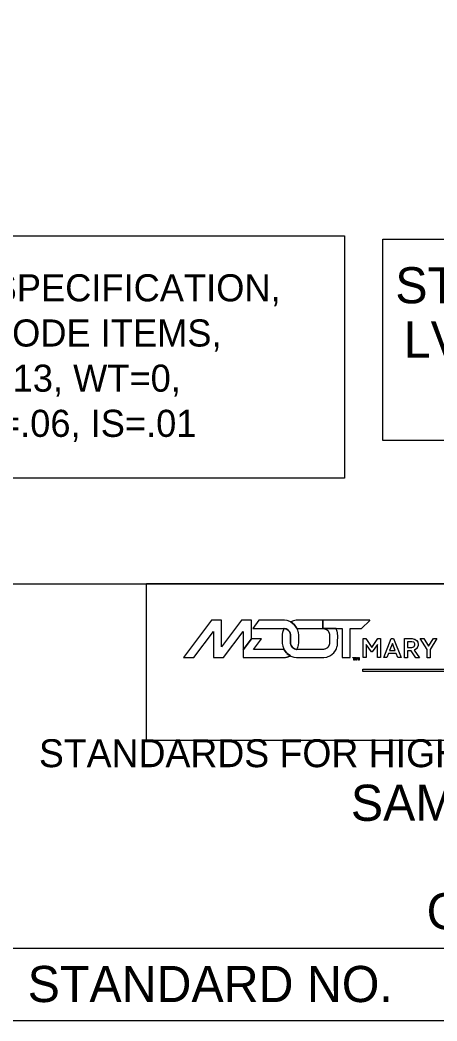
# Model space of a CAD drawing. Extents: x -0.5 to 19.9, y 5.2 to 17.3.
# Drawn here: x 3.628 to 5.013, y 5.937 to 9.261 of the extents above; entities that cross this region are included whole.
import ezdxf

# ---------------------------------------------------------------- set-up
doc = ezdxf.new("R2010")
doc.units = 0
for name, color, linetype in [('BORD-LINE', 7, 'Continuous'), ('DETL-NOTE', 7, 'Continuous'), ('MSHA-LOGO', 7, 'Continuous'), ('TTLB-TEXT', 7, 'Continuous'), ('USER-BORD', 7, 'Continuous'), ('USER-LINE', 7, 'Continuous')]:
    doc.layers.add(name, color=color, linetype=linetype)

msp = doc.modelspace()

# ---------------------------------------------------------------- linework, layer by layer
at = {"layer": 'BORD-LINE'}
msp.add_line((7.7685, 7.3883), (0.3943, 7.3883), dxfattribs=at)
at = {"layer": 'MSHA-LOGO'}
for points in [[(4.3697, 7.1699), (4.3968, 7.206), (4.3968, 7.2687), (4.3638, 7.2687), (4.3434, 7.2413), (4.2975, 7.1802), (4.2975, 7.2687), (4.2646, 7.2687), (4.1714, 7.1444), (4.2053, 7.1444), (4.2704, 7.2312), (4.2704, 7.1444), (4.3046, 7.1444), (4.3697, 7.2312)], [(4.5048, 7.2408), (4.5056, 7.2408), (4.5132, 7.2388), (4.5139, 7.2384), (4.5147, 7.238), (4.5185, 7.2352), (4.5217, 7.2319), (4.5223, 7.2312), (4.5229, 7.2303), (4.5251, 7.2256), (4.5263, 7.2205), (4.5264, 7.2195), (4.5264, 7.2195), (4.5264, 7.2193), (4.5264, 7.2193), (4.5264, 7.219), (4.5264, 7.2184), (4.5264, 7.2182), (4.5264, 7.1947), (4.5264, 7.1944), (4.5264, 7.1938), (4.5264, 7.1936), (4.5264, 7.1936), (4.5264, 7.1934), (4.5264, 7.1934), (4.5264, 7.1929), (4.5262, 7.1918), (4.5262, 7.1914), (4.5265, 7.1894), (4.5287, 7.1838), (4.5334, 7.1776), (4.5402, 7.1731), (4.5463, 7.1712), (4.5476, 7.1711), (4.5479, 7.1715), (4.5481, 7.1717), (4.5481, 7.1717), (4.5483, 7.1722), (4.5503, 7.1766), (4.5505, 7.1771), (4.5506, 7.1776), (4.552, 7.1823), (4.5522, 7.1828), (4.5522, 7.183), (4.5528, 7.1854), (4.5529, 7.1857), (4.553, 7.1864), (4.5537, 7.1927), (4.5537, 7.1948), (4.5537, 7.2179), (4.5537, 7.2202), (4.553, 7.2263), (4.5529, 7.227), (4.5528, 7.2273), (4.5523, 7.2297), (4.5522, 7.23), (4.552, 7.2304), (4.5506, 7.2352), (4.5505, 7.2356), (4.5503, 7.2361), (4.5483, 7.2406), (4.5481, 7.241), (4.5468, 7.2433), (4.5389, 7.2535), (4.5287, 7.2615), (4.5264, 7.2627), (4.5247, 7.2636), (4.5155, 7.2668), (4.5066, 7.2682), (4.5036, 7.2682), (4.4217, 7.2682), (4.4013, 7.241), (4.5036, 7.241), (4.5037, 7.2409), (4.5045, 7.2408)], [(4.5482, 7.2406), (4.5487, 7.2406), (4.5489, 7.2406), (4.6329, 7.2406), (4.633, 7.2406), (4.6333, 7.2406), (4.6334, 7.2406), (4.6335, 7.241), (4.6335, 7.268), (4.6335, 7.268), (4.633, 7.268), (4.6329, 7.268), (4.5489, 7.268), (4.5459, 7.268), (4.537, 7.2666), (4.5278, 7.2634), (4.5264, 7.2627), (4.5287, 7.2615), (4.5389, 7.2535), (4.5468, 7.2433), (4.5481, 7.241)], [(4.6335, 7.268), (4.6335, 7.2408), (4.6979, 7.2408), (4.6979, 7.1444), (4.7249, 7.1444), (4.7249, 7.2408), (4.7625, 7.2408), (4.7895, 7.2678), (4.7895, 7.268)], [(4.5269, 7.1499), (4.5268, 7.1499), (4.5266, 7.15), (4.5266, 7.1501), (4.5254, 7.1507), (4.5151, 7.1582), (4.5142, 7.1592), (4.5133, 7.1601), (4.5059, 7.1703), (4.5053, 7.1714), (4.5052, 7.1714), (4.5049, 7.1714), (4.5048, 7.1714), (4.5045, 7.1714), (4.5038, 7.1714), (4.5036, 7.1714), (4.4042, 7.1714), (4.4306, 7.2064), (4.3966, 7.2064), (4.3695, 7.1704), (4.3695, 7.1442), (4.5034, 7.1442), (4.5042, 7.1442), (4.5062, 7.1443), (4.5065, 7.1444), (4.5072, 7.1444), (4.5092, 7.1447), (4.5094, 7.1447), (4.5096, 7.1447), (4.5101, 7.1449), (4.5103, 7.1449), (4.5104, 7.1449), (4.512, 7.1452), (4.5122, 7.1452), (4.5124, 7.1452), (4.513, 7.1454), (4.5132, 7.1454), (4.5133, 7.1455), (4.5148, 7.1457), (4.5149, 7.1457), (4.515, 7.1458), (4.5158, 7.1461), (4.5159, 7.1461), (4.5161, 7.1461), (4.5174, 7.1466), (4.5175, 7.1466), (4.5176, 7.1467), (4.5184, 7.1469), (4.5185, 7.1469), (4.5186, 7.147), (4.5199, 7.1474), (4.5201, 7.1475), (4.5201, 7.1475), (4.521, 7.1478), (4.5211, 7.1478), (4.5212, 7.1479), (4.5227, 7.1485), (4.5228, 7.1485), (4.5229, 7.1485), (4.5236, 7.1488), (4.5237, 7.1489), (4.5239, 7.1489), (4.5259, 7.1499), (4.5261, 7.1501), (4.5262, 7.15), (4.5267, 7.1499)], [(4.7677, 7.2075), (4.7766, 7.2075), (4.7968, 7.1779), (4.8165, 7.2075), (4.825, 7.2075), (4.825, 7.144), (4.8152, 7.144), (4.8152, 7.1881), (4.7978, 7.1628), (4.7952, 7.1628), (4.7775, 7.1881), (4.7775, 7.144), (4.7677, 7.144)], [(4.8613, 7.2075), (4.8688, 7.2075), (4.8937, 7.144), (4.8832, 7.144), (4.8777, 7.1582), (4.8518, 7.1582), (4.8463, 7.144), (4.8361, 7.144)], [(4.8558, 7.1674), (4.8744, 7.1674), (4.8649, 7.1914)], [(4.9052, 7.1437), (4.9052, 7.2072), (4.9274, 7.2072), (4.9302, 7.2072), (4.9377, 7.2058), (4.9386, 7.2055), (4.9393, 7.2053), (4.945, 7.2014), (4.9454, 7.2009), (4.9458, 7.2004), (4.9488, 7.1952), (4.949, 7.1947), (4.9492, 7.1941), (4.95, 7.1889), (4.95, 7.1871), (4.95, 7.1842), (4.9473, 7.1764), (4.9467, 7.1756), (4.9462, 7.1748), (4.9385, 7.169), (4.9376, 7.1687), (4.9546, 7.1433), (4.9425, 7.1433), (4.9271, 7.1667), (4.915, 7.1667), (4.915, 7.1433), (4.9052, 7.1433)], [(4.915, 7.197), (4.915, 7.1776), (4.9278, 7.1776), (4.9299, 7.1776), (4.936, 7.1798), (4.9366, 7.1802), (4.9371, 7.1806), (4.9399, 7.186), (4.9399, 7.1878), (4.9399, 7.1895), (4.9374, 7.1943), (4.9369, 7.1947), (4.9364, 7.1951), (4.9297, 7.197), (4.9274, 7.197)], [(4.9899, 7.1713), (4.9899, 7.1437), (4.9801, 7.1437), (4.9801, 7.1713), (4.9572, 7.2075), (4.9693, 7.2075), (4.985, 7.1822), (5.0011, 7.2075), (5.0128, 7.2075)], [(4.7335, 7.1444), (4.7424, 7.1444), (4.7424, 7.1428), (4.739, 7.1428), (4.739, 7.1354), (4.7372, 7.1354), (4.7372, 7.1428), (4.7335, 7.1428)], [(4.7436, 7.1444), (4.7452, 7.1444), (4.7491, 7.14), (4.7527, 7.1444), (4.7544, 7.1444), (4.7544, 7.1354), (4.7523, 7.1354), (4.7523, 7.1418), (4.7489, 7.1377), (4.7455, 7.1418), (4.7455, 7.1354), (4.7436, 7.1354)], [(4.7668, 7.1057), (6.8835, 7.1057), (6.8835, 7.0979), (4.7668, 7.0979)]]:
    msp.add_lwpolyline(points, close=True, dxfattribs=at)
for points in [[(4.5264, 7.205), (4.5264, 7.2179), (4.5264, 7.2183), (4.5264, 7.219), (4.5264, 7.2193), (4.5264, 7.2198), (4.5266, 7.221), (4.5266, 7.2214), (4.5265, 7.2223), (4.5231, 7.2306), (4.5226, 7.2313), (4.5221, 7.2321), (4.5188, 7.2356), (4.5149, 7.2383), (4.5141, 7.2387), (4.5133, 7.2391), (4.5058, 7.2411), (4.505, 7.2412), (4.505, 7.2411), (4.5048, 7.2408), (4.5044, 7.2402), (4.5017, 7.2334), (4.5015, 7.2327), (4.5014, 7.2325), (4.5007, 7.2301), (4.5007, 7.2298), (4.5005, 7.2288), (4.4993, 7.2206), (4.4993, 7.2179), (4.4993, 7.205), (4.4993, 7.2036)], [(4.4993, 7.2036), (4.4993, 7.194), (4.4993, 7.191), (4.5007, 7.182), (4.5039, 7.1728), (4.5048, 7.1711), (4.5054, 7.1699), (4.513, 7.1594), (4.5139, 7.1585), (4.5148, 7.1576), (4.5253, 7.15), (4.5264, 7.1494), (4.5281, 7.1485), (4.5373, 7.1453), (4.5463, 7.1439), (4.5492, 7.1439), (4.6332, 7.1439), (4.6367, 7.1439), (4.6472, 7.1458), (4.6596, 7.1514), (4.6699, 7.16), (4.6761, 7.1681), (4.6777, 7.1711), (4.6778, 7.1713), (4.6788, 7.1734), (4.6789, 7.1736), (4.679, 7.1741), (4.6806, 7.1784), (4.6808, 7.1788), (4.6808, 7.1791), (4.6816, 7.1817), (4.6816, 7.1819), (4.6816, 7.1821), (4.6816, 7.1823), (4.6817, 7.1824), (4.6821, 7.1843), (4.6821, 7.1845), (4.6821, 7.1847), (4.6823, 7.1851), (4.6823, 7.1852), (4.6823, 7.1854), (4.6826, 7.1871), (4.6827, 7.1872), (4.6827, 7.1873), (4.6827, 7.1875), (4.6827, 7.1876), (4.6827, 7.1877), (4.6827, 7.188), (4.6827, 7.1881), (4.6827, 7.1886), (4.6828, 7.1898), (4.6828, 7.1902), (4.6828, 7.1909), (4.6828, 7.191), (4.6828, 7.1918), (4.683, 7.1934), (4.683, 7.194), (4.6832, 7.2179)], [(4.6832, 7.2179), (4.6832, 7.2186), (4.683, 7.2206), (4.683, 7.2208), (4.683, 7.221), (4.683, 7.2217), (4.683, 7.2222), (4.6828, 7.2234), (4.6828, 7.2238), (4.6828, 7.2239), (4.6828, 7.2242), (4.6828, 7.2243), (4.6828, 7.2244), (4.6828, 7.2246), (4.6828, 7.2246), (4.6828, 7.2248), (4.6825, 7.2265), (4.6825, 7.2267), (4.6825, 7.2269), (4.6823, 7.2273), (4.6823, 7.2274), (4.6823, 7.2276), (4.6818, 7.2294), (4.6818, 7.2296), (4.6818, 7.2298), (4.6818, 7.23), (4.6817, 7.2302), (4.681, 7.2328), (4.6809, 7.2331), (4.6808, 7.2335), (4.6792, 7.2378), (4.679, 7.2382), (4.679, 7.2384), (4.6779, 7.2406), (4.6779, 7.2408), (4.6779, 7.2409), (4.6777, 7.2412), (4.6342, 7.2412), (4.6341, 7.2408), (4.6346, 7.2408), (4.6348, 7.2408), (4.635, 7.2408), (4.6355, 7.2407), (4.6356, 7.2406), (4.636, 7.2406), (4.6394, 7.2399), (4.6397, 7.2398), (4.64, 7.2397), (4.6429, 7.2387), (4.6432, 7.2386), (4.6433, 7.2385), (4.6449, 7.2376), (4.6451, 7.2375), (4.6452, 7.2375), (4.6452, 7.2375), (4.6454, 7.2375), (4.6468, 7.2366), (4.6469, 7.2365), (4.6471, 7.2364), (4.6471, 7.2363), (4.6472, 7.2362), (4.6485, 7.2353), (4.6487, 7.2351), (4.6488, 7.235), (4.649, 7.2349), (4.65, 7.2338), (4.65, 7.2337), (4.6502, 7.2336), (4.6502, 7.2336), (4.6504, 7.2334), (4.6505, 7.2333), (4.6512, 7.2325), (4.6512, 7.2324), (4.6514, 7.2322), (4.6514, 7.2322), (4.6517, 7.2317), (4.6518, 7.2317), (4.6518, 7.2316), (4.6526, 7.2306), (4.6526, 7.2305), (4.6527, 7.2304), (4.6529, 7.2299), (4.653, 7.2298), (4.6531, 7.2296), (4.6531, 7.2296), (4.6532, 7.2295), (4.6536, 7.2287), (4.6536, 7.2286), (4.6537, 7.2285), (4.6539, 7.2278), (4.654, 7.2277), (4.654, 7.2276), (4.6545, 7.2266), (4.6545, 7.2265), (4.6545, 7.2265), (4.6547, 7.2258), (4.6547, 7.2257), (4.6548, 7.2255), (4.6548, 7.2255), (4.6549, 7.2254), (4.6552, 7.2247), (4.6552, 7.2244), (4.6552, 7.2244), (4.6555, 7.2233), (4.6555, 7.2232), (4.6555, 7.223), (4.6557, 7.2224), (4.6557, 7.2222), (4.6557, 7.2221), (4.6559, 7.2211), (4.6559, 7.2208), (4.6559, 7.2206), (4.656, 7.2201), (4.656, 7.22), (4.656, 7.2194), (4.6562, 7.2182), (4.6562, 7.2177), (4.6562, 7.1941), (4.6562, 7.1936), (4.6561, 7.1921), (4.656, 7.1919), (4.656, 7.1917), (4.6559, 7.1911), (4.6559, 7.191), (4.6559, 7.1907), (4.6557, 7.1899), (4.6557, 7.1897), (4.6557, 7.1894), (4.6555, 7.1888), (4.6555, 7.1886), (4.6555, 7.1885), (4.6552, 7.1875), (4.6552, 7.1874), (4.6551, 7.1873), (4.6549, 7.1865), (4.6548, 7.1864), (4.6548, 7.1863), (4.6547, 7.1861), (4.6547, 7.186), (4.6545, 7.1855), (4.6545, 7.1854), (4.6545, 7.1853), (4.654, 7.1843), (4.654, 7.1842), (4.6539, 7.1841), (4.6537, 7.1834), (4.6536, 7.1833), (4.6536, 7.1832), (4.6532, 7.1823), (4.6531, 7.1823), (4.653, 7.1821), (4.653, 7.1821), (4.6529, 7.182), (4.6527, 7.1815), (4.6526, 7.1814), (4.6525, 7.1813), (4.6518, 7.1803), (4.6518, 7.1802), (4.6517, 7.1802), (4.6514, 7.1797), (4.6514, 7.1797), (4.6512, 7.1795), (4.6511, 7.1794), (4.6504, 7.1786), (4.6504, 7.1785), (4.6502, 7.1783), (4.6501, 7.1781), (4.65, 7.1781), (4.65, 7.178), (4.6489, 7.177), (4.6488, 7.1769), (4.6487, 7.1767), (4.6485, 7.1767), (4.6472, 7.1756), (4.6471, 7.1755), (4.6469, 7.1754), (4.6469, 7.1754), (4.6468, 7.1753), (4.6454, 7.1744), (4.6452, 7.1743), (4.6451, 7.1743), (4.6451, 7.1743), (4.6449, 7.1743), (4.6433, 7.1734), (4.6432, 7.1733), (4.6429, 7.1732), (4.64, 7.1722), (4.6397, 7.1721), (4.6394, 7.172), (4.636, 7.1713), (4.6356, 7.1712), (4.6354, 7.1712), (4.6348, 7.1711), (4.6348, 7.1711), (4.6345, 7.1711), (4.6338, 7.1711), (4.6335, 7.1711), (4.5496, 7.1711), (4.5493, 7.1711), (4.5486, 7.1711), (4.5484, 7.1711), (4.5463, 7.1712), (4.5402, 7.1731), (4.5335, 7.1778), (4.5288, 7.1845), (4.5269, 7.1905), (4.5268, 7.1926), (4.5268, 7.1929), (4.5268, 7.1937), (4.5268, 7.194), (4.5268, 7.205), (4.5264, 7.205)]]:
    msp.add_lwpolyline(points, dxfattribs=at)
at = {"layer": 'TTLB-TEXT'}
msp.add_line((7.7685, 7.3883), (0.3943, 7.3883), dxfattribs=at)
for points in [[(0.3943, 16.2906), (7.7685, 16.2906), (7.7685, 5.9375), (0.3943, 5.9375)], [(2.4865, 8.5442), (4.7055, 8.5442), (4.7055, 7.74), (2.4865, 7.74)], [(4.8334, 8.534), (7.5921, 8.534), (7.5921, 7.8648), (4.8334, 7.8648)]]:
    msp.add_lwpolyline(points, close=True, dxfattribs=at)
at = {"layer": 'USER-BORD'}
for p, q in [((7.7685, 7.3883), (0.3943, 7.3883)), ((3.2956, 6.1793), (7.7685, 6.1793))]:
    msp.add_line(p, q, dxfattribs=at)
at = {"layer": 'USER-LINE'}
msp.add_lwpolyline([(7.0197, 6.8692), (4.0486, 6.8692), (4.0486, 7.3899), (7.0197, 7.3899)], close=True, dxfattribs=at)

# ---------------------------------------------------------------- texts
at = {"layer": 'DETL-NOTE'}
msp.add_text('STANDARDS FOR HIGHWAYS AND INCIDENTAL STRUCTURES', height=0.09269, dxfattribs=at).set_placement((3.6914, 6.7803))
at = {"layer": 'TTLB-TEXT'}
for s, height, p in [('STANDARD DESCR., NUMBER  ', 0.12, (4.8745, 8.3205)), ('SPECIFICATION,', 0.09, (3.5376, 8.327)), (' CATEGORY CODE ITEMS, ', 0.09, (2.7731, 8.177)), ('LV=13, WT=0, CO=0, FT=30, ', 0.12, (4.9028, 8.1405)), ('FT=30, TX=.09, LV=13, WT=0,', 0.09, (2.5102, 8.027)), (' CO=0, LS=.06, IS=.01', 0.09, (2.9933, 7.877)), ('STANDARDS FOR HIGHWAYS AND INCIDENTAL STRUCTURES', 0.09269, (3.6913, 6.7802)), ('STANDARDS FOR HIGHWAYS AND INCIDENTAL STRUCTURES', 0.09269, (3.6914, 6.7803)), ('SAMPLE STANDARD', 0.12, (4.727, 6.6021)), ('GOES HERE  ', 0.12, (4.9786, 6.2421)), ('STANDARD NO.', 0.12, (3.6538, 6.0003))]:
    msp.add_text(s, height=height, dxfattribs=at).set_placement(p)

doc.saveas('drawing.dxf')
